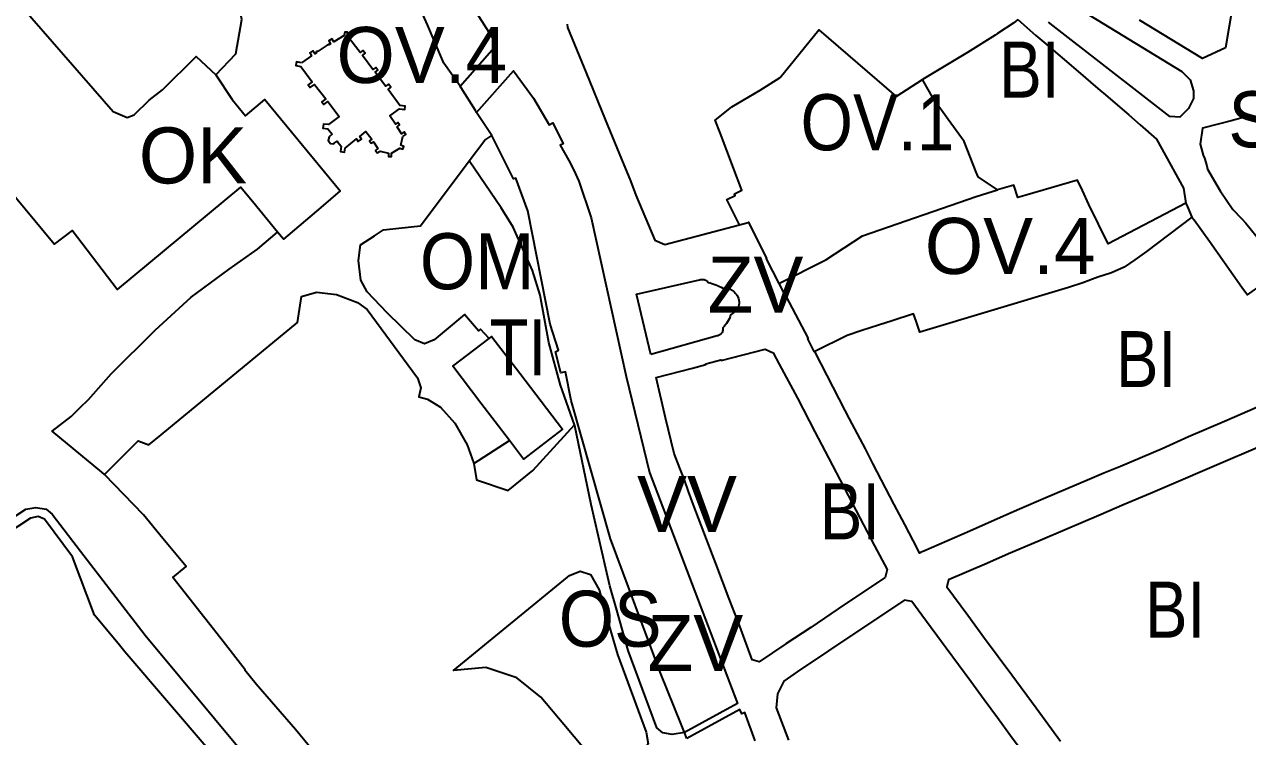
# Model space of a CAD drawing. Extents: x -650451 to -642268, y -1075216 to -1066610.
# Drawn here: x -647351.3 to -647023.9, y -1071089.1 to -1070898.5 of the extents above; entities that cross this region are included whole.
import ezdxf

# ---------------------------------------------------------------- set-up
doc = ezdxf.new("R2010")
doc.units = 0
doc.header["$LTSCALE"] = 6
doc.layers.add('1', color=7, linetype='Continuous', lineweight=35)
doc.layers.add('2', color=7, linetype='Continuous')

msp = doc.modelspace()

# ---------------------------------------------------------------- linework, layer by layer
at = {"layer": '1'}
for p, q in [((-647226.17, -1070928.21), (-647230.25, -1070922.01)), ((-647231.03, -1071015.96), (-647221.48, -1071009.84)), ((-647174.03, -1071089.6), (-647174.64, -1071088.01))]:
    msp.add_line(p, q, dxfattribs=at)
for points in [[(-647234.692, -1070915.011), (-647224.85, -1070903.83), (-647230.18, -1070895.42), (-647234.96, -1070886.44), (-647239.25, -1070875.22), (-647242.25, -1070862.17), (-647243.66, -1070845.66), (-647239.62, -1070773.47), (-647239.86, -1070761.48), (-647241.3, -1070749.53), (-647241.85, -1070745.57), (-647240.98, -1070745.38), (-647241.85, -1070740.97), (-647242.7, -1070741.08), (-647245.52, -1070731.47), (-647246.06, -1070729.62), (-647257.01, -1070736.43), (-647257.7, -1070736.849)], [(-647234.692, -1070915.011), (-647239.03, -1070908.78), (-647239.55, -1070907.58), (-647243.43, -1070898.6), (-647247.23, -1070889.94), (-647248.7, -1070886.62), (-647250.56, -1070882.4), (-647254.39, -1070869.52), (-647255.83, -1070861.83), (-647256.25, -1070855.85), (-647256.68, -1070852.52), (-647256.57, -1070838.54), (-647255.98, -1070822.28), (-647255.9, -1070820.31), (-647255.46, -1070814.32), (-647253.9, -1070795.28), (-647252.5, -1070774.26), (-647252.79, -1070760.71), (-647254, -1070751.57), (-647256.78, -1070739.92), (-647257.02, -1070739.07), (-647257.7, -1070736.849)], [(-647300.07, -1070911.99), (-647294.73, -1070906.32), (-647293.09, -1070897.18), (-647293.7, -1070893.99), (-647299.98, -1070891.49), (-647318.68, -1070842.72), (-647316.06, -1070835.75), (-647318.44, -1070829.76), (-647321.01, -1070827.14), (-647324.15, -1070826.29), (-647331.02, -1070829.74), (-647345.71, -1070837.13), (-647359.71, -1070844.27), (-647403.51, -1070866.6)], [(-647283.54, -1070954.02), (-647290.28, -1070945.89), (-647293.51, -1070942.01), (-647326.51, -1070969.42), (-647338.57, -1070953.63), (-647343.34, -1070957.27), (-647396.9, -1070892.8), (-647402.82, -1070885.66), (-647405.34, -1070881.23), (-647398.52, -1070877.49)], [(-647398.52, -1070877.49), (-647396.63, -1070881.62), (-647397.24, -1070881.95), (-647395.52, -1070884.04), (-647387.99, -1070880.11), (-647383.09, -1070880.09), (-647358.76, -1070890.4), (-647354.79, -1070890.4), (-647327.54, -1070921.72), (-647323.84, -1070923.35), (-647321.91, -1070922.61), (-647317.93, -1070918.75), (-647314.33, -1070915.95), (-647305.3, -1070907.01), (-647300.07, -1070911.99)], [(-647071.49, -1070892.79), (-647041.52, -1070911.06), (-647039.23, -1070913.32), (-647038.36, -1070916.27), (-647038.35, -1070918.28), (-647039.69, -1070920.97), (-647042.06, -1070923.25), (-647044.71, -1070923.08), (-647050.33, -1070918.71), (-647075.9, -1070898.84), (-647077.16, -1070897.85)], [(-647027.85, -1070893.09), (-647029.81, -1070904.76), (-647035.98, -1070907.53), (-647052.83, -1070897.35)], [(-647206.05, -1070898.36), (-647205.89, -1070899.27), (-647200.92, -1070911.38), (-647195.82, -1070923.93), (-647191.5, -1070934.48), (-647189.1, -1070940.36), (-647187.61, -1070944.13), (-647182.58, -1070956.24), (-647179.88, -1070957.38), (-647159.85, -1070952.1)], [(-647085.4, -1070897.14), (-647086.47, -1070898), (-647090.87, -1070900.84), (-647091.46, -1070901.32), (-647098.82, -1070905.97), (-647110.92, -1070913.23)], [(-647085.4, -1070897.14), (-647080.53, -1070901.41), (-647078.43, -1070903.2), (-647069.27, -1070911.03), (-647063.93, -1070915.6), (-647062.93, -1070916.46), (-647062.48, -1070916.84), (-647055.69, -1070922.66), (-647052.6, -1070925.35), (-647048.23, -1070929.16), (-647041.01, -1070942.31), (-647040.4, -1070946.32)], [(-647159.85, -1070952.1), (-647163.28, -1070945.32), (-647161.07, -1070944.22), (-647161.27, -1070943.82), (-647159.26, -1070942.81), (-647161.48, -1070936.91), (-647165.05, -1070927.47), (-647166.38, -1070924.05), (-647165.6, -1070923.42), (-647161.98, -1070920.55), (-647154.33, -1070916.01), (-647148.98, -1070912.65), (-647138.65, -1070899.94), (-647117.95, -1070917.77), (-647110.92, -1070913.23)], [(-647300.07, -1070911.99), (-647295.69, -1070918.55), (-647292.14, -1070922.88), (-647286.92, -1070918.59), (-647266.79, -1070942.95), (-647271.95, -1070947.47), (-647281.97, -1070955.9), (-647283.54, -1070954.02)], [(-647230.25, -1070922.01), (-647220.39, -1070910.9), (-647215.03, -1070918.17), (-647210.86, -1070925.29), (-647209.82, -1070924.75), (-647207.09, -1070930.4), (-647207.86, -1070930.75), (-647205.57, -1070934.86), (-647204.22, -1070937.43), (-647202.86, -1070940.4), (-647199.63, -1070950.26), (-647190.24, -1070992.73), (-647184, -1071018.37), (-647160.4, -1071080.2), (-647174.64, -1071088.01)], [(-647230.25, -1070922.01), (-647230.57, -1070921.5), (-647234.4, -1070915.43), (-647234.692, -1070915.011)], [(-647090.82, -1070942.76), (-647095.97, -1070939.29), (-647096.5, -1070937.98), (-647099.76, -1070929.83), (-647104.06, -1070923.89), (-647107.9, -1070918.58), (-647110.92, -1070913.23)], [(-647022.68, -1070922.89), (-647024.74, -1070923.29), (-647028.24, -1070924.23), (-647031.79, -1070925.16), (-647035.97, -1070926.21), (-647036.57, -1070930.47), (-647035.81, -1070933.45), (-647035.45, -1070934.25), (-647034.83, -1070936.33), (-647034.59, -1070937.16), (-647031.19, -1070942.96), (-647027.84, -1070947.96), (-647025.53, -1070950.4), (-647024.34, -1070951.65), (-647020.12, -1070956.86)], [(-647232.24, -1070934.94), (-647228.1, -1070929.42), (-647226.17, -1070928.21)], [(-647174.64, -1071088.01), (-647175.35, -1071086.17), (-647181.14, -1071071.84), (-647194.45, -1071036.17), (-647204.93, -1070999.15), (-647206.44, -1070991.45), (-647207.7, -1070991.72), (-647209.12, -1070986.08), (-647208.38, -1070985.66), (-647210.6, -1070978.71), (-647216.55, -1070948.32), (-647219.79, -1070939.58), (-647220.36, -1070939.77), (-647226.17, -1070928.21)], [(-647226.9, -1070982.49), (-647229.19, -1070979.99), (-647229.76, -1070980.48), (-647233.51, -1070976.06), (-647238.43, -1070980.23), (-647241.61, -1070982.89), (-647244.18, -1070983.97), (-647246.77, -1070982.85), (-647254.21, -1070975.66), (-647259.57, -1070970.02), (-647261.23, -1070966.89), (-647261.84, -1070961.66), (-647261.35, -1070957.45), (-647257.62, -1070955.02), (-647255.21, -1070953.46), (-647251.11, -1070953.01), (-647245.32, -1070952.38), (-647232.24, -1070934.94)], [(-647204.055, -1071005.609), (-647207.77, -1070995.03), (-647210.97, -1070983.56), (-647213.23, -1070970.92), (-647215.29, -1070964.36), (-647220.46, -1070952.68), (-647223.65, -1070947.55), (-647232.24, -1070934.94)], [(-647040.4, -1070946.32), (-647061.16, -1070957.22), (-647066.38, -1070946.67), (-647068.07, -1070942.91), (-647069.41, -1070940.13), (-647083.51, -1070944.2), (-647085.35, -1070944.79), (-647086.45, -1070941.45), (-647090.82, -1070942.76)], [(-647149.39, -1070967.8), (-647136.81, -1070961.5), (-647126.93, -1070955.01), (-647096.57, -1070944.49), (-647090.82, -1070942.76)], [(-647040.4, -1070946.32), (-647039.98, -1070947.27), (-647038.77, -1070950.05)], [(-647159.85, -1070952.1), (-647157.59, -1070951.46), (-647157.5, -1070951.41), (-647152.62, -1070961.11), (-647152.75, -1070961.18), (-647149.39, -1070967.8)], [(-647038.77, -1070950.05), (-647050.95, -1070959.26), (-647054.07, -1070961.43), (-647056.94, -1070963.42), (-647060.27, -1070964.9), (-647063.97, -1070966.14), (-647067.95, -1070967.65), (-647071.8, -1070968.86), (-647111.62, -1070980.84), (-647112.64, -1070977.86), (-647113.29, -1070975.92), (-647118.98, -1070977.8), (-647122.66, -1070978.98), (-647127.1, -1070980.41), (-647131.11, -1070981.71), (-647139.77, -1070986.03)], [(-647038.77, -1070950.05), (-647038.19, -1070950.73), (-647034.09, -1070956.5), (-647030.03, -1070962.2), (-647025.43, -1070968.74), (-647023.92, -1070970.83), (-647019.89, -1070967.94)], [(-647329.84, -1071018.95), (-647330.62, -1071018.31), (-647343.92, -1071007.28), (-647338.79, -1071003.38), (-647336.36, -1071001.01), (-647334.18, -1070998.88), (-647328.1, -1070992.01), (-647316.29, -1070980.27), (-647306.66, -1070971.47), (-647296.48, -1070964), (-647295.01, -1070962.93), (-647288.96, -1070958.57), (-647283.54, -1070954.02)], [(-647149.39, -1070967.8), (-647147.59, -1070971.24), (-647147.47, -1070971.18), (-647141.54, -1070982.55), (-647141.67, -1070982.64), (-647139.98, -1070986.03), (-647139.82, -1070985.92), (-647139.77, -1070986.03)], [(-647329.84, -1071018.95), (-647322.32, -1071011.35), (-647320.83, -1071009.87), (-647317.99, -1071010.98), (-647314.7, -1071008.28), (-647278.2, -1070978.19), (-647277.18, -1070971.26), (-647273.13, -1070970.1), (-647267.79, -1070970.77), (-647262.13, -1070972.9), (-647259.55, -1070974.78), (-647246.12, -1070993.07), (-647245.18, -1070995.74), (-647245.72, -1070998.15), (-647243.42, -1070998.75), (-647239.96, -1071000.87), (-647236.09, -1071005.2), (-647232.83, -1071010.95), (-647231.03, -1071015.96)], [(-647221.48, -1071009.84), (-647229.16, -1070999.79), (-647236.67, -1070989.95), (-647226.9, -1070982.49)], [(-647226.9, -1070982.49), (-647226.22, -1070981.97), (-647226.17, -1070982.03), (-647218.71, -1070991.81), (-647207.27, -1071006.79), (-647217.72, -1071014.77), (-647221.48, -1071009.84)], [(-647015.04, -1070998.19), (-647030.09, -1071004.71), (-647039.7, -1071008.85), (-647046.73, -1071012.03), (-647057.91, -1071016.75), (-647062.38, -1071018.6), (-647066.72, -1071020.44), (-647077.91, -1071025.19), (-647084.94, -1071028.2), (-647088.61, -1071029.83), (-647098.03, -1071034.02), (-647098.25, -1071034.12), (-647110.53, -1071039.41), (-647111.46, -1071039.83), (-647111.69, -1071039.93), (-647112.2, -1071038.81), (-647115.64, -1071032.28), (-647118.46, -1071026.92), (-647123.01, -1071018.21), (-647124.16, -1071016), (-647126.2, -1071012.05), (-647130.42, -1071003.99), (-647131.57, -1071001.79), (-647136.42, -1070992.4), (-647139.77, -1070986.03)], [(-647231.03, -1071015.96), (-647230.29, -1071020.37), (-647221.81, -1071023.24), (-647215.22, -1071017.87), (-647204.055, -1071005.609)], [(-647174.64, -1071088.01), (-647177.94, -1071088.5), (-647180.4, -1071088.08), (-647181.99, -1071086.74), (-647189.68, -1071065.99), (-647192.72, -1071055.27), (-647194.61, -1071048.68), (-647195.64, -1071044.04), (-647199.63, -1071026.94), (-647203.96, -1071005.88), (-647204.055, -1071005.609)], [(-647018.62, -1071010.61), (-647034.05, -1071017.19), (-647042.97, -1071021.07), (-647049.89, -1071023.99), (-647056.91, -1071026.94), (-647063.71, -1071029.85), (-647072.13, -1071033.43), (-647080, -1071036.81), (-647087.87, -1071040.16), (-647093.7, -1071042.7), (-647103.94, -1071047.15), (-647104.42, -1071049.02), (-647098.81, -1071056.61), (-647094.28, -1071062.75), (-647086.95, -1071072.55), (-647080.49, -1071081.41), (-647074, -1071090.26)], [(-647272.93, -1071094.24), (-647278.77, -1071087.15), (-647289.31, -1071075.05), (-647292.31, -1071071.29), (-647292.21, -1071071.21), (-647298.74, -1071062.85), (-647311.58, -1071046.44), (-647308, -1071043.56), (-647314.3, -1071036.01), (-647319.46, -1071029.7), (-647329.84, -1071018.95)], [(-647387.4, -1071052.29), (-647350.96, -1071028.22), (-647348.28, -1071027.76), (-647345.5, -1071028.22), (-647343.87, -1071029.5), (-647336.29, -1071039.43), (-647319.03, -1071061.93), (-647291.18, -1071095.4), (-647287.15, -1071103.31), (-647283.88, -1071107.77), (-647268.68, -1071126.13), (-647263.88, -1071130.58), (-647255.57, -1071136.67), (-647224.08, -1071173.41), (-647229.71, -1071178.23)], [(-647229.71, -1071178.23), (-647234.12, -1071172.97), (-647236.41, -1071170.41), (-647239.35, -1071166.98), (-647245.43, -1071159.88), (-647267.4, -1071133.54), (-647272.8, -1071134.42), (-647292.31, -1071111.16), (-647290.44, -1071106.08), (-647324.46, -1071066.41), (-647326.18, -1071064.18), (-647332.55, -1071056.58), (-647338.47, -1071040.94), (-647345.94, -1071030.88), (-647347.66, -1071030.16), (-647349.67, -1071030.64), (-647386.3, -1071054.58)], [(-647083.72, -1071093.74), (-647087.31, -1071088.82), (-647090.86, -1071084.05), (-647094.36, -1071079.2), (-647097.98, -1071074.28), (-647104.55, -1071065.44), (-647111.07, -1071056.53), (-647113.73, -1071052.94), (-647115.73, -1071052.54), (-647127.7, -1071060.49), (-647144.46, -1071071.76), (-647148, -1071074.23), (-647149.73, -1071077.63), (-647150.04, -1071081.39), (-647146.78, -1071090.05)], [(-647155.66, -1071090.17), (-647158.43, -1071082.62), (-647159.3, -1071082.95), (-647159.77, -1071081.77), (-647174.03, -1071089.6)]]:
    msp.add_lwpolyline(points, dxfattribs=at)
for points in [[(-647277.17, -1070908.69), (-647278.48, -1070908.49), (-647278.62, -1070909.45), (-647277.36, -1070909.69), (-647274.24, -1070913.79), (-647275.33, -1070914.65), (-647274.8, -1070915.35), (-647273.64, -1070914.56), (-647270.63, -1070918.36), (-647271.67, -1070919.15), (-647271.13, -1070919.89), (-647270.06, -1070919.11), (-647267.03, -1070923.07), (-647269.92, -1070925.25), (-647271.28, -1070925.13), (-647271.47, -1070926.21), (-647270.08, -1070926.39), (-647268.97, -1070927.86), (-647269.77, -1070928.5), (-647269.99, -1070929.52), (-647269.38, -1070930.33), (-647268.44, -1070930.38), (-647268.41, -1070930.23), (-647267.62, -1070929.66), (-647267.47, -1070929.87), (-647266.56, -1070931.06), (-647266.72, -1070932.46), (-647265.63, -1070932.62), (-647265.43, -1070931.54), (-647262.44, -1070929.09), (-647262, -1070929.75), (-647261.09, -1070929.13), (-647261.53, -1070928.48), (-647259.89, -1070927.15), (-647258.29, -1070929.18), (-647258.97, -1070929.62), (-647258.53, -1070930.27), (-647257.88, -1070929.92), (-647256.71, -1070931.7), (-647257.29, -1070932.16), (-647256.9, -1070932.86), (-647256.12, -1070932.38), (-647253.82, -1070932.94), (-647253.82, -1070933.83), (-647253.02, -1070933.84), (-647253.01, -1070932.93), (-647250.86, -1070931.53), (-647250.03, -1070931.88), (-647249.73, -1070931.15), (-647250.53, -1070930.81), (-647250.45, -1070930.43), (-647250.01, -1070928.45), (-647249.19, -1070927.88), (-647249.68, -1070927.24), (-647250.33, -1070927.71), (-647251.52, -1070925.85), (-647250.9, -1070925.37), (-647251.34, -1070924.71), (-647251.99, -1070925.14), (-647253.45, -1070922.94), (-647250.89, -1070921.03), (-647249.5, -1070921.21), (-647249.38, -1070920.3), (-647250.79, -1070920.11), (-647253.98, -1070915.85), (-647253.23, -1070915.24), (-647253.51, -1070914.87), (-647253.82, -1070914.48), (-647254.63, -1070915.01), (-647257.46, -1070911.24), (-647256.7, -1070910.69), (-647257.25, -1070909.94), (-647258.03, -1070910.5), (-647260.85, -1070906.74), (-647260.1, -1070906.16), (-647260.68, -1070905.41), (-647261.45, -1070905.98), (-647264.87, -1070901.6), (-647264.79, -1070900.57), (-647265.58, -1070900.5), (-647265.7, -1070901.42), (-647268.46, -1070903.14), (-647268.97, -1070902.33), (-647269.79, -1070902.81), (-647269.36, -1070903.61), (-647269.84, -1070903.95), (-647269.95, -1070903.74), (-647270.55, -1070904.18), (-647272.68, -1070905.57), (-647273.21, -1070905.82), (-647273.09, -1070906.05), (-647273.59, -1070906.36), (-647274.14, -1070905.56), (-647274.92, -1070906.06), (-647274.42, -1070906.88)], [(-647183.62, -1070986.82), (-647187.45, -1070970.63), (-647170.63, -1070966.83), (-647170.332, -1070966.732), (-647170.007, -1070966.683), (-647169.669, -1070966.69), (-647169.332, -1070966.757), (-647169.013, -1070966.883), (-647168.724, -1070967.059), (-647168.478, -1070967.276), (-647168.28, -1070967.52), (-647167.768, -1070967.644), (-647167.259, -1070967.788), (-647166.756, -1070967.952), (-647166.259, -1070968.136), (-647165.77, -1070968.339), (-647165.29, -1070968.561), (-647164.82, -1070968.802), (-647164.36, -1070969.06), (-647164.089, -1070969.042), (-647163.813, -1070969.042), (-647163.534, -1070969.062), (-647163.253, -1070969.103), (-647162.972, -1070969.164), (-647162.695, -1070969.246), (-647162.423, -1070969.349), (-647162.158, -1070969.471), (-647161.903, -1070969.613), (-647161.66, -1070969.773), (-647161.431, -1070969.949), (-647161.216, -1070970.14), (-647161.018, -1070970.343), (-647160.837, -1070970.558), (-647160.674, -1070970.78), (-647160.53, -1070971.01), (-647160.324, -1070971.382), (-647160.163, -1070971.788), (-647160.055, -1070972.219), (-647160.004, -1070972.664), (-647160.012, -1070973.112), (-647160.079, -1070973.551), (-647160.201, -1070973.97), (-647160.37, -1070974.36), (-647160.556, -1070974.633), (-647160.761, -1070974.896), (-647160.981, -1070975.147), (-647161.218, -1070975.384), (-647161.468, -1070975.606), (-647161.732, -1070975.812), (-647162.006, -1070976), (-647162.29, -1070976.17), (-647162.432, -1070976.658), (-647162.612, -1070977.138), (-647162.828, -1070977.607), (-647163.079, -1070978.058), (-647163.364, -1070978.49), (-647163.679, -1070978.898), (-647164.023, -1070979.279), (-647164.39, -1070979.63), (-647164.362, -1070979.795), (-647164.349, -1070979.968), (-647164.353, -1070980.147), (-647164.374, -1070980.329), (-647164.415, -1070980.512), (-647164.475, -1070980.692), (-647164.555, -1070980.868), (-647164.653, -1070981.035), (-647164.768, -1070981.19), (-647164.897, -1070981.333), (-647165.04, -1070981.459), (-647165.191, -1070981.569), (-647165.35, -1070981.66), (-647165.513, -1070981.734), (-647165.677, -1070981.79), (-647165.84, -1070981.83)], [(-647120.88, -1071046.5), (-647131.8, -1071053.75), (-647140.81, -1071059.84), (-647147.46, -1071064.28), (-647154.59, -1071069.06), (-647156.48, -1071068.56), (-647159.8, -1071059.54), (-647162.69, -1071052.17), (-647166.23, -1071042.76), (-647168.69, -1071036.25), (-647172.26, -1071026.85), (-647173.5, -1071023.44), (-647174.63, -1071020.34), (-647175.82, -1071017.26), (-647177.35, -1071013.31), (-647179.69, -1071003.72), (-647182.23, -1070992.92), (-647172.48, -1070990.42), (-647168.86, -1070989.48), (-647168.9, -1070989.33), (-647164.9, -1070988.27), (-647164.84, -1070988.42), (-647153.01, -1070985.33), (-647150.85, -1070986.34), (-647149.25, -1070989.35), (-647144.4, -1070998.49), (-647139.72, -1071007.46), (-647136.1, -1071014.48), (-647131.87, -1071022.49), (-647127.72, -1071030.49), (-647123.72, -1071037.99), (-647120.35, -1071044.37)], [(-647205.93, -1071046.39), (-647205.41, -1071045.94), (-647202.51, -1071044.83), (-647199.79, -1071045.64), (-647197.45, -1071049.77), (-647195.66, -1071056.4), (-647192.57, -1071067.1), (-647184.91, -1071087.86), (-647184.33, -1071090.96), (-647185.4, -1071092.65), (-647196.26, -1071098.46), (-647206.93, -1071085.87), (-647213.06, -1071078.47), (-647219.48, -1071073.34), (-647227.79, -1071070.53), (-647236.42, -1071071.34)]]:
    msp.add_lwpolyline(points, close=True, dxfattribs=at)

# ---------------------------------------------------------------- texts
at = {"layer": '2'}
for s, p in [('OV.4', (-647267.76, -1070914.13)), ('OK', (-647320.67, -1070941.01)), ('OV.4', (-647110.271, -1070965.24)), ('ZV', (-647168.408, -1070975.575)), ('VV', (-647187.326, -1071034.307)), ('ZV', (-647184.521, -1071071.516))]:
    msp.add_text(s, height=15, dxfattribs=at).set_placement(p)
for s, width, p in [('BI', 0.85, (-647090.359, -1070918.047)), ('OV.1', 0.9, (-647143.546, -1070932.14)), ('SM', 0.95, (-647029.032, -1070931.345)), ('OM', 0.95, (-647245.47, -1070969.34)), ('TI', 0.85, (-647226.796, -1070992.384)), ('BI', 0.85, (-647059.116, -1070995.535)), ('BI', 0.85, (-647138.39, -1071036.283)), ('OS', 0.95, (-647208.28, -1071065.01)), ('BI', 0.85, (-647051.337, -1071062.584))]:
    msp.add_text(s, height=15, dxfattribs=dict(at, width=width)).set_placement(p)

doc.saveas('drawing.dxf')
